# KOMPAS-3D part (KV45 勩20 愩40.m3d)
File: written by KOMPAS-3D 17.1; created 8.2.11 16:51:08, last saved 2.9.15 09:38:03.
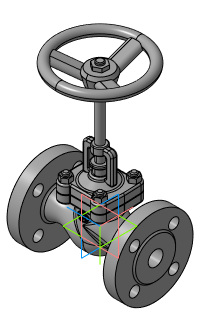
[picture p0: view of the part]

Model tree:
1. Ось X
2. Ось Y
3. Ось Z
4. Операция без истории:2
